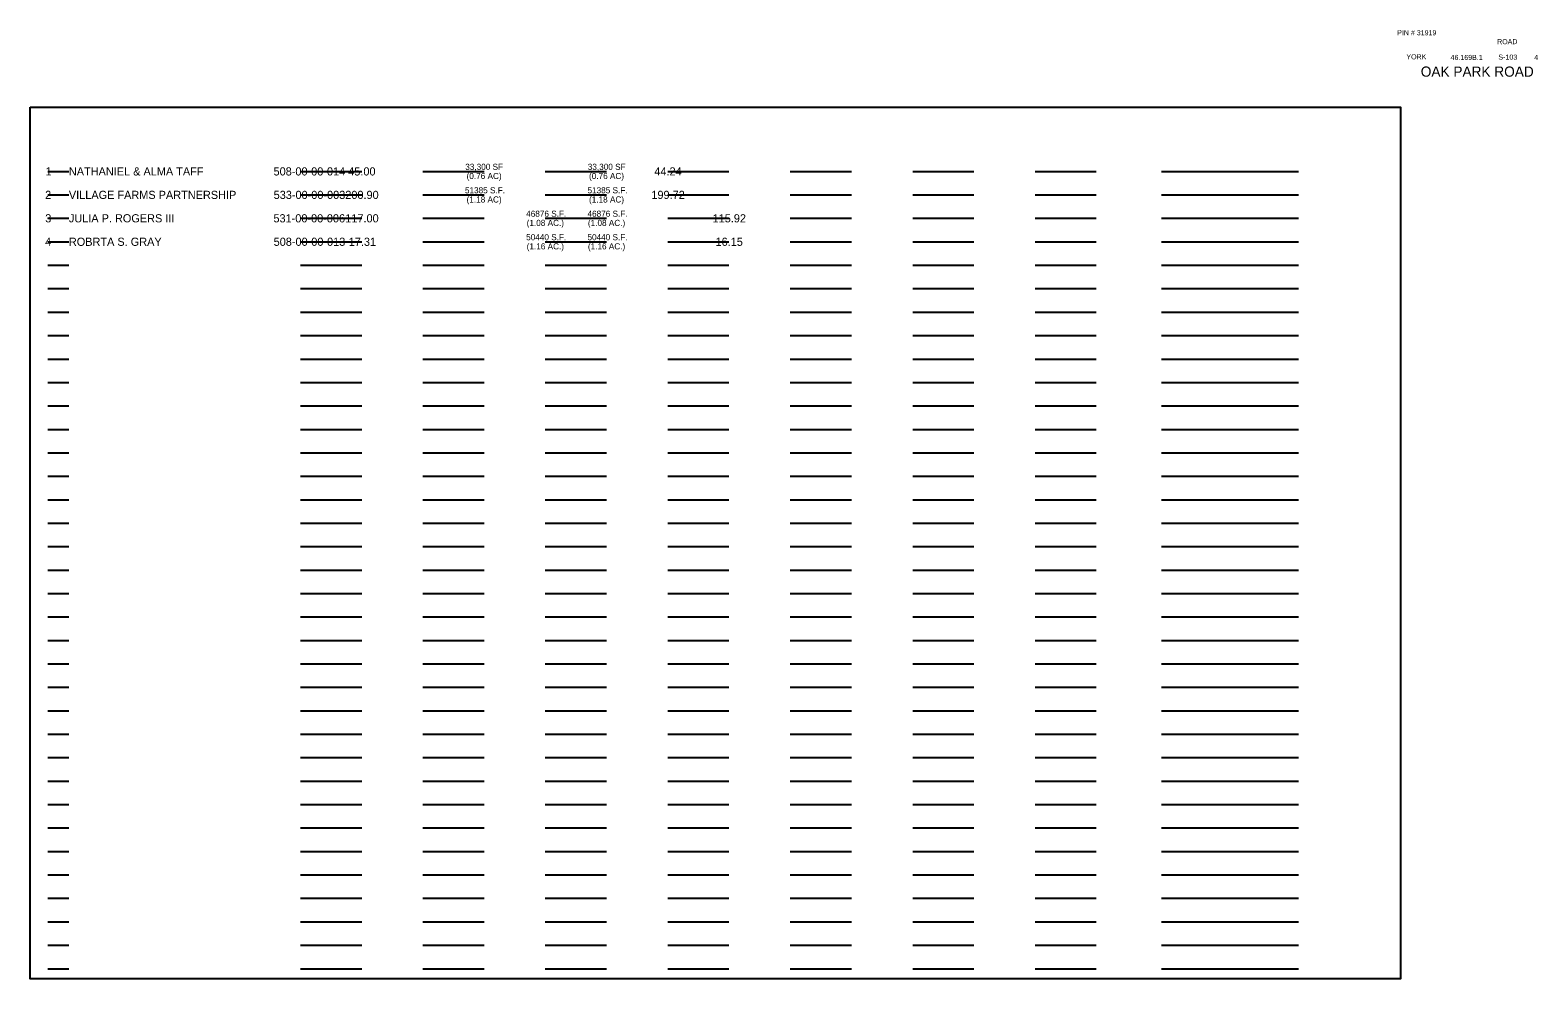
# Model space of a CAD drawing. Extents: x 13328 to 14805, y 15875 to 16806.
import ezdxf

# ---------------------------------------------------------------- set-up
doc = ezdxf.new("R2010")
doc.units = 0
doc.layers.add('Level 41', color=7, linetype='Continuous')
doc.layers.add('Level 45', color=7, linetype='Continuous')

msp = doc.modelspace()

# ---------------------------------------------------------------- linework, layer by layer
at = {"layer": 'Level 45'}
for p, q in [((13345, 16667), (13365.5, 16667)), ((13592.5, 16667), (13652.5, 16667)), ((13712.4, 16667), (13772.4, 16667)), ((13832.4, 16667), (13892.4, 16667)), ((13952.4, 16667), (14012.4, 16667)), ((14072.5, 16667), (14132.5, 16667)), ((14192.5, 16667), (14252.5, 16667)), ((14312.5, 16667), (14372.5, 16667)), ((14436.5, 16667), (14570.5, 16667)), ((13345, 16644), (13365.5, 16644)), ((13592.5, 16644), (13652.5, 16644)), ((13712.4, 16644), (13772.4, 16644)), ((13832.4, 16644), (13892.4, 16644)), ((13952.4, 16644), (14012.4, 16644)), ((14072.5, 16644), (14132.5, 16644)), ((14192.5, 16644), (14252.5, 16644)), ((14312.5, 16644), (14372.5, 16644)), ((14436.5, 16644), (14570.5, 16644)), ((13345, 16621), (13365.5, 16621)), ((13592.5, 16621), (13652.5, 16621)), ((13712.4, 16621), (13772.4, 16621)), ((13832.4, 16621), (13892.4, 16621)), ((13952.4, 16621), (14012.4, 16621)), ((14072.5, 16621), (14132.5, 16621)), ((14192.5, 16621), (14252.5, 16621)), ((14312.5, 16621), (14372.5, 16621)), ((14436.5, 16621), (14570.5, 16621)), ((13345, 16598), (13365.5, 16598)), ((13592.5, 16598), (13652.5, 16598)), ((13712.4, 16598), (13772.4, 16598)), ((13832.4, 16598), (13892.4, 16598)), ((13952.4, 16598), (14012.4, 16598)), ((14072.5, 16598), (14132.5, 16598)), ((14192.5, 16598), (14252.5, 16598)), ((14312.5, 16598), (14372.5, 16598)), ((14436.5, 16598), (14570.5, 16598)), ((13345, 16575), (13365.5, 16575)), ((13592.5, 16575), (13652.5, 16575)), ((13712.4, 16575), (13772.4, 16575)), ((13832.4, 16575), (13892.4, 16575)), ((13952.4, 16575), (14012.4, 16575)), ((14072.5, 16575), (14132.5, 16575)), ((14192.5, 16575), (14252.5, 16575)), ((14312.5, 16575), (14372.5, 16575)), ((14436.5, 16575), (14570.5, 16575)), ((13345, 16552), (13365.5, 16552)), ((13592.5, 16552), (13652.5, 16552)), ((13712.4, 16552), (13772.4, 16552)), ((13832.4, 16552), (13892.4, 16552)), ((13952.4, 16552), (14012.4, 16552)), ((14072.5, 16552), (14132.5, 16552)), ((14192.5, 16552), (14252.5, 16552)), ((14312.5, 16552), (14372.5, 16552)), ((14436.5, 16552), (14570.5, 16552)), ((13345, 16529), (13365.5, 16529)), ((13592.5, 16529), (13652.5, 16529)), ((13712.4, 16529), (13772.4, 16529)), ((13832.4, 16529), (13892.4, 16529)), ((13952.4, 16529), (14012.4, 16529)), ((14072.5, 16529), (14132.5, 16529)), ((14192.5, 16529), (14252.5, 16529)), ((14312.5, 16529), (14372.5, 16529)), ((14436.5, 16529), (14570.5, 16529)), ((13345, 16506), (13365.5, 16506)), ((13592.5, 16506), (13652.5, 16506)), ((13712.4, 16506), (13772.4, 16506)), ((13832.4, 16506), (13892.4, 16506)), ((13952.4, 16506), (14012.4, 16506)), ((14072.5, 16506), (14132.5, 16506)), ((14192.5, 16506), (14252.5, 16506)), ((14312.5, 16506), (14372.5, 16506)), ((14436.5, 16506), (14570.5, 16506)), ((13345, 16483), (13365.5, 16483)), ((13592.5, 16483), (13652.5, 16483)), ((13712.4, 16483), (13772.4, 16483)), ((13832.4, 16483), (13892.4, 16483)), ((13952.4, 16483), (14012.4, 16483)), ((14072.5, 16483), (14132.5, 16483)), ((14192.5, 16483), (14252.5, 16483)), ((14312.5, 16483), (14372.5, 16483)), ((14436.5, 16483), (14570.5, 16483)), ((13345, 16460), (13365.5, 16460)), ((13592.5, 16460), (13652.5, 16460)), ((13712.4, 16460), (13772.4, 16460)), ((13832.4, 16460), (13892.4, 16460)), ((13952.4, 16460), (14012.4, 16460)), ((14072.5, 16460), (14132.5, 16460)), ((14192.5, 16460), (14252.5, 16460)), ((14312.5, 16460), (14372.5, 16460)), ((14436.5, 16460), (14570.5, 16460)), ((13345, 16437), (13365.5, 16437)), ((13592.5, 16437), (13652.5, 16437)), ((13712.4, 16437), (13772.4, 16437)), ((13832.4, 16437), (13892.4, 16437)), ((13952.4, 16437), (14012.4, 16437)), ((14072.5, 16437), (14132.5, 16437)), ((14192.5, 16437), (14252.5, 16437)), ((14312.5, 16437), (14372.5, 16437)), ((14436.5, 16437), (14570.5, 16437)), ((13345, 16414), (13365.5, 16414)), ((13592.5, 16414), (13652.5, 16414)), ((13712.4, 16414), (13772.4, 16414)), ((13832.4, 16414), (13892.4, 16414)), ((13952.4, 16414), (14012.4, 16414)), ((14072.5, 16414), (14132.5, 16414)), ((14192.5, 16414), (14252.5, 16414)), ((14312.5, 16414), (14372.5, 16414)), ((14436.5, 16414), (14570.5, 16414)), ((13345, 16391), (13365.5, 16391)), ((13592.5, 16391), (13652.5, 16391)), ((13712.4, 16391), (13772.4, 16391)), ((13832.4, 16391), (13892.4, 16391)), ((13952.4, 16391), (14012.4, 16391)), ((14072.5, 16391), (14132.5, 16391)), ((14192.5, 16391), (14252.5, 16391)), ((14312.5, 16391), (14372.5, 16391)), ((14436.5, 16391), (14570.5, 16391)), ((13345, 16368), (13365.5, 16368)), ((13592.5, 16368), (13652.5, 16368)), ((13712.4, 16368), (13772.4, 16368)), ((13832.4, 16368), (13892.4, 16368)), ((13952.4, 16368), (14012.4, 16368)), ((14072.5, 16368), (14132.5, 16368)), ((14192.5, 16368), (14252.5, 16368)), ((14312.5, 16368), (14372.5, 16368)), ((14436.5, 16368), (14570.5, 16368)), ((13345, 16345), (13365.5, 16345)), ((13592.5, 16345), (13652.5, 16345)), ((13712.4, 16345), (13772.4, 16345)), ((13832.4, 16345), (13892.4, 16345)), ((13952.4, 16345), (14012.4, 16345)), ((14072.5, 16345), (14132.5, 16345)), ((14192.5, 16345), (14252.5, 16345)), ((14312.5, 16345), (14372.5, 16345)), ((14436.5, 16345), (14570.5, 16345)), ((13345, 16322), (13365.5, 16322)), ((13592.5, 16322), (13652.5, 16322)), ((13712.4, 16322), (13772.4, 16322)), ((13832.4, 16322), (13892.4, 16322)), ((13952.4, 16322), (14012.4, 16322)), ((14072.5, 16322), (14132.5, 16322)), ((14192.5, 16322), (14252.5, 16322)), ((14312.5, 16322), (14372.5, 16322)), ((14436.5, 16322), (14570.5, 16322)), ((13345, 16299), (13365.5, 16299)), ((13592.5, 16299), (13652.5, 16299)), ((13712.4, 16299), (13772.4, 16299)), ((13832.4, 16299), (13892.4, 16299)), ((13952.4, 16299), (14012.4, 16299)), ((14072.5, 16299), (14132.5, 16299)), ((14192.5, 16299), (14252.5, 16299)), ((14312.5, 16299), (14372.5, 16299)), ((14436.5, 16299), (14570.5, 16299)), ((13345, 16276), (13365.5, 16276)), ((13592.5, 16276), (13652.5, 16276)), ((13712.4, 16276), (13772.4, 16276)), ((13832.4, 16276), (13892.4, 16276)), ((13952.4, 16276), (14012.4, 16276)), ((14072.5, 16276), (14132.5, 16276)), ((14192.5, 16276), (14252.5, 16276)), ((14312.5, 16276), (14372.5, 16276)), ((14436.5, 16276), (14570.5, 16276)), ((13345, 16253), (13365.5, 16253)), ((13592.5, 16253), (13652.5, 16253)), ((13712.4, 16253), (13772.4, 16253)), ((13832.4, 16253), (13892.4, 16253)), ((13952.4, 16253), (14012.4, 16253)), ((14072.5, 16253), (14132.5, 16253)), ((14192.5, 16253), (14252.5, 16253)), ((14312.5, 16253), (14372.5, 16253)), ((14436.5, 16253), (14570.5, 16253)), ((13345, 16230), (13365.5, 16230)), ((13592.5, 16230), (13652.5, 16230)), ((13712.4, 16230), (13772.4, 16230)), ((13832.4, 16230), (13892.4, 16230)), ((13952.4, 16230), (14012.4, 16230)), ((14072.5, 16230), (14132.5, 16230)), ((14192.5, 16230), (14252.5, 16230)), ((14312.5, 16230), (14372.5, 16230)), ((14436.5, 16230), (14570.5, 16230)), ((13345, 16207), (13365.5, 16207)), ((13592.5, 16207), (13652.5, 16207)), ((13712.4, 16207), (13772.4, 16207)), ((13832.4, 16207), (13892.4, 16207)), ((13952.4, 16207), (14012.4, 16207)), ((14072.5, 16207), (14132.5, 16207)), ((14192.5, 16207), (14252.5, 16207)), ((14312.5, 16207), (14372.5, 16207)), ((14436.5, 16207), (14570.5, 16207)), ((13345, 16184), (13365.5, 16184)), ((13592.5, 16184), (13652.5, 16184)), ((13712.4, 16184), (13772.4, 16184)), ((13832.4, 16184), (13892.4, 16184)), ((13952.4, 16184), (14012.4, 16184)), ((14072.5, 16184), (14132.5, 16184)), ((14192.5, 16184), (14252.5, 16184)), ((14312.5, 16184), (14372.5, 16184)), ((14436.5, 16184), (14570.5, 16184)), ((13345, 16161), (13365.5, 16161)), ((13592.5, 16161), (13652.5, 16161)), ((13712.4, 16161), (13772.4, 16161)), ((13832.4, 16161), (13892.4, 16161)), ((13952.4, 16161), (14012.4, 16161)), ((14072.5, 16161), (14132.5, 16161)), ((14192.5, 16161), (14252.5, 16161)), ((14312.5, 16161), (14372.5, 16161)), ((14436.5, 16161), (14570.5, 16161)), ((13345, 16138), (13365.5, 16138)), ((13592.5, 16138), (13652.5, 16138)), ((13712.4, 16138), (13772.4, 16138)), ((13832.4, 16138), (13892.4, 16138)), ((13952.4, 16138), (14012.4, 16138)), ((14072.5, 16138), (14132.5, 16138)), ((14192.5, 16138), (14252.5, 16138)), ((14312.5, 16138), (14372.5, 16138)), ((14436.5, 16138), (14570.5, 16138)), ((13345, 16115), (13365.5, 16115)), ((13592.5, 16115), (13652.5, 16115)), ((13712.4, 16115), (13772.4, 16115)), ((13832.4, 16115), (13892.4, 16115)), ((13952.4, 16115), (14012.4, 16115)), ((14072.5, 16115), (14132.5, 16115)), ((14192.5, 16115), (14252.5, 16115)), ((14312.5, 16115), (14372.5, 16115)), ((14436.5, 16115), (14570.5, 16115)), ((13345, 16092), (13365.5, 16092)), ((13592.5, 16092), (13652.5, 16092)), ((13712.4, 16092), (13772.4, 16092)), ((13832.4, 16092), (13892.4, 16092)), ((13952.4, 16092), (14012.4, 16092)), ((14072.5, 16092), (14132.5, 16092)), ((14192.5, 16092), (14252.5, 16092)), ((14312.5, 16092), (14372.5, 16092)), ((14436.5, 16092), (14570.5, 16092)), ((13345, 16069), (13365.5, 16069)), ((13592.5, 16069), (13652.5, 16069)), ((13712.4, 16069), (13772.4, 16069)), ((13832.4, 16069), (13892.4, 16069)), ((13952.4, 16069), (14012.4, 16069)), ((14072.5, 16069), (14132.5, 16069)), ((14192.5, 16069), (14252.5, 16069)), ((14312.5, 16069), (14372.5, 16069)), ((14436.5, 16069), (14570.5, 16069)), ((13345, 16046), (13365.5, 16046)), ((13592.5, 16046), (13652.5, 16046)), ((13712.4, 16046), (13772.4, 16046)), ((13832.4, 16046), (13892.4, 16046)), ((13952.4, 16046), (14012.4, 16046)), ((14072.5, 16046), (14132.5, 16046)), ((14192.5, 16046), (14252.5, 16046)), ((14312.5, 16046), (14372.5, 16046)), ((14436.5, 16046), (14570.5, 16046)), ((13345, 16023), (13365.5, 16023)), ((13592.5, 16023), (13652.5, 16023)), ((13712.4, 16023), (13772.4, 16023)), ((13832.4, 16023), (13892.4, 16023)), ((13952.4, 16023), (14012.4, 16023)), ((14072.5, 16023), (14132.5, 16023)), ((14192.5, 16023), (14252.5, 16023)), ((14312.5, 16023), (14372.5, 16023)), ((14436.5, 16023), (14570.5, 16023)), ((13345, 16000), (13365.5, 16000)), ((13592.5, 16000), (13652.5, 16000)), ((13712.4, 16000), (13772.4, 16000)), ((13832.4, 16000), (13892.4, 16000)), ((13952.4, 16000), (14012.4, 16000)), ((14072.5, 16000), (14132.5, 16000)), ((14192.5, 16000), (14252.5, 16000)), ((14312.5, 16000), (14372.5, 16000)), ((14436.5, 16000), (14570.5, 16000)), ((13345, 15977), (13365.5, 15977)), ((13592.5, 15977), (13652.5, 15977)), ((13712.4, 15977), (13772.4, 15977)), ((13832.4, 15977), (13892.4, 15977)), ((13952.4, 15977), (14012.4, 15977)), ((14072.5, 15977), (14132.5, 15977)), ((14192.5, 15977), (14252.5, 15977)), ((14312.5, 15977), (14372.5, 15977)), ((14436.5, 15977), (14570.5, 15977)), ((13345, 15954), (13365.5, 15954)), ((13592.5, 15954), (13652.5, 15954)), ((13712.4, 15954), (13772.4, 15954)), ((13832.4, 15954), (13892.4, 15954)), ((13952.4, 15954), (14012.4, 15954)), ((14072.5, 15954), (14132.5, 15954)), ((14192.5, 15954), (14252.5, 15954)), ((14312.5, 15954), (14372.5, 15954)), ((14436.5, 15954), (14570.5, 15954)), ((13345, 15931), (13365.5, 15931)), ((13592.5, 15931), (13652.5, 15931)), ((13712.4, 15931), (13772.4, 15931)), ((13832.4, 15931), (13892.4, 15931)), ((13952.4, 15931), (14012.4, 15931)), ((14072.5, 15931), (14132.5, 15931)), ((14192.5, 15931), (14252.5, 15931)), ((14312.5, 15931), (14372.5, 15931)), ((14436.5, 15931), (14570.5, 15931)), ((13345, 15908), (13365.5, 15908)), ((13592.5, 15908), (13652.5, 15908)), ((13712.4, 15908), (13772.4, 15908)), ((13832.4, 15908), (13892.4, 15908)), ((13952.4, 15908), (14012.4, 15908)), ((14072.5, 15908), (14132.5, 15908)), ((14192.5, 15908), (14252.5, 15908)), ((14312.5, 15908), (14372.5, 15908)), ((14436.5, 15908), (14570.5, 15908)), ((13345, 15885), (13365.5, 15885)), ((13592.5, 15885), (13652.5, 15885)), ((13712.4, 15885), (13772.4, 15885)), ((13832.4, 15885), (13892.4, 15885)), ((13952.4, 15885), (14012.4, 15885)), ((14072.5, 15885), (14132.5, 15885)), ((14192.5, 15885), (14252.5, 15885)), ((14312.5, 15885), (14372.5, 15885)), ((14436.5, 15885), (14570.5, 15885))]:
    msp.add_line(p, q, dxfattribs=at)
msp.add_lwpolyline([(13327.5, 16730), (14670.5, 16730), (14670.5, 15875), (13327.5, 15875)], close=True, dxfattribs=at)

# ---------------------------------------------------------------- texts
at = {"layer": 'Level 41'}
for s, height, p in [('PIN # 31919', 5, (14667.4, 16800.5)), ('ROAD', 5, (14765.3, 16791.8)), ('YORK', 5, (14676.4, 16776.9)), ('46.169B.1', 5, (14719.7, 16776.3)), ('S-103', 5, (14766.6, 16776.6)), ('4', 5, (14801.7, 16776.3)), ('OAK PARK ROAD', 10, (14690.5, 16759.9)), ('1', 8, (13342.6, 16663)), ('NATHANIEL & ALMA TAFF', 8, (13365.5, 16663)), ('508-00-00-014', 8, (13566.1, 16663)), ('45.00', 8, (13639.3, 16663)), ('33,300 SF', 6, (13754, 16668.5)), ('33,300 SF', 6, (13874.1, 16668.5)), ('44.24', 8, (13939.3, 16663)), ('(0.76 AC)', 6, (13755.3, 16659.5)), ('(0.76 AC)', 6, (13875.3, 16659.5)), ('2', 8, (13342.2, 16640)), ('VILLAGE FARMS PARTNERSHIP', 8, (13365.5, 16640)), ('533-00-00-003', 8, (13566.2, 16640)), ('200.90', 8, (13636.4, 16640)), ('51385 S.F.', 6, (13753.7, 16645.5)), ('(1.18 AC)', 6, (13755.3, 16636.5)), ('51385 S.F.', 6, (13873.8, 16645.5)), ('(1.18 AC)', 6, (13875.3, 16636.5)), ('199.72', 8, (13936.4, 16640)), ('3', 8, (13342.3, 16617)), ('JULIA P. ROGERS III', 8, (13365.5, 16617)), ('531-00-00-006', 8, (13566, 16617)), ('117.00', 8, (13636.4, 16617)), ('46876 S.F.', 6, (13813.7, 16622.5)), ('46876 S.F.', 6, (13873.8, 16622.5)), ('115.92', 8, (13996.4, 16617)), ('(1.08 AC.)', 6, (13814.2, 16613.5)), ('(1.08 AC.)', 6, (13874.2, 16613.5)), ('4', 8, (13342.2, 16594)), ('ROBRTA S. GRAY', 8, (13365.5, 16594)), ('508-00-00-013', 8, (13566.2, 16594)), ('17.31', 8, (13639.8, 16594)), ('50440 S.F.', 6, (13813.7, 16599.5)), ('(1.16 AC.)', 6, (13814.2, 16590.5)), ('50440 S.F.', 6, (13873.8, 16599.5)), ('(1.16 AC.)', 6, (13874.2, 16590.5)), ('16.15', 8, (13999.3, 16594))]:
    msp.add_text(s, height=height, dxfattribs=at).set_placement(p)

doc.saveas('drawing.dxf')
